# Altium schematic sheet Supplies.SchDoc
size A4
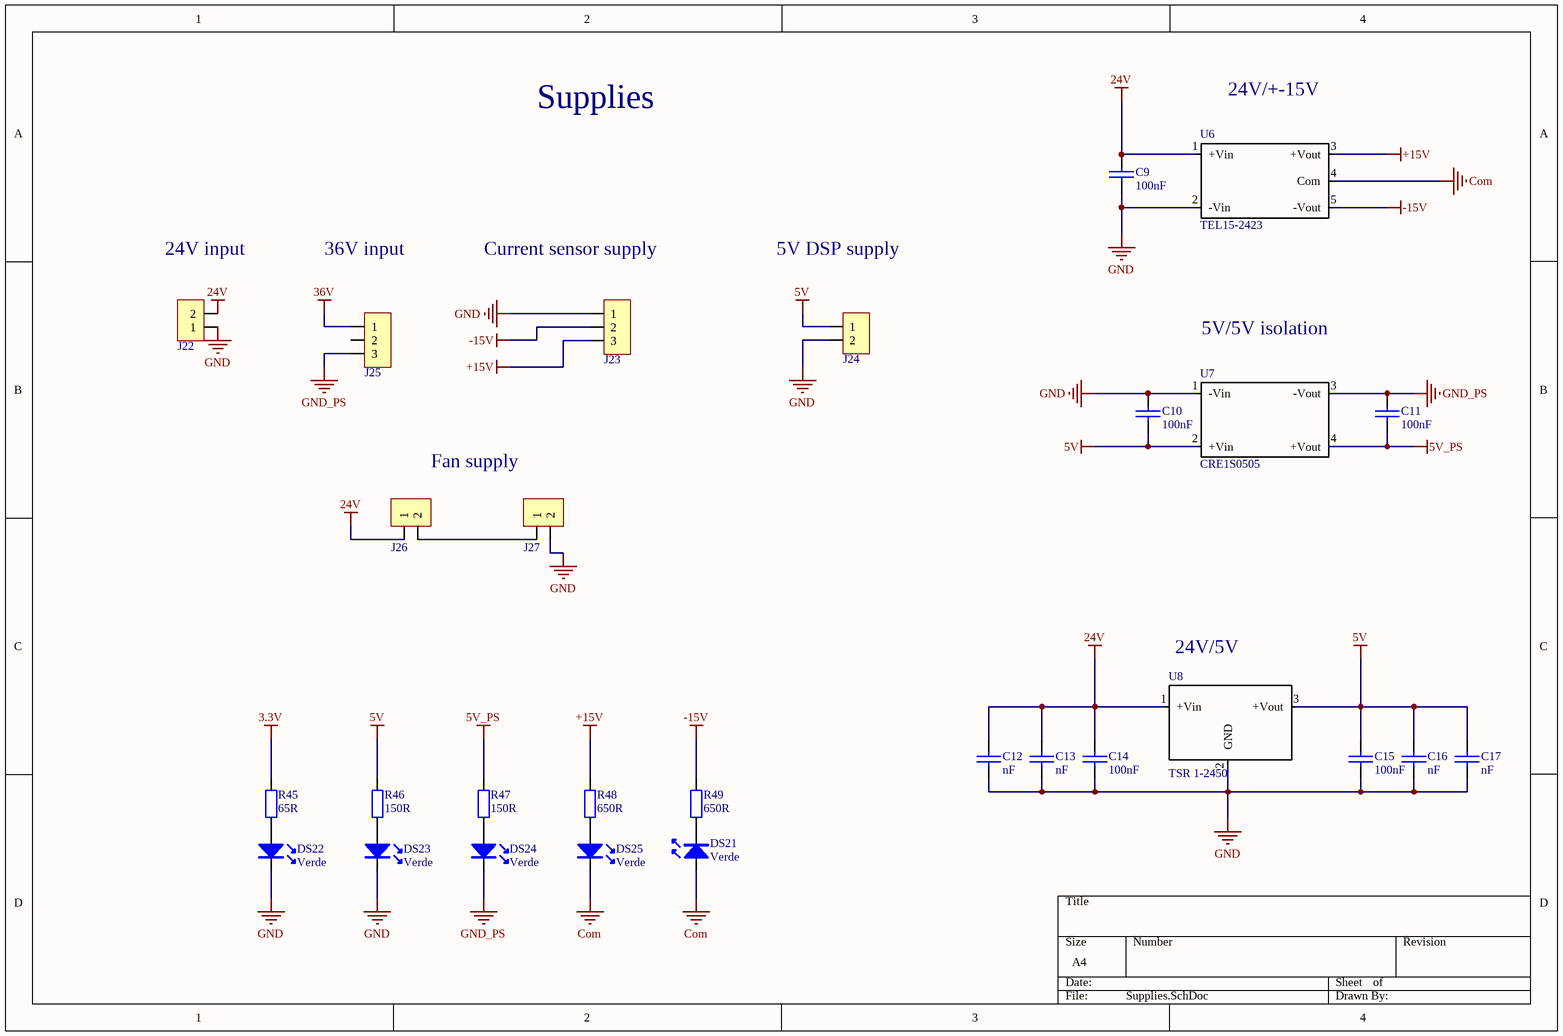
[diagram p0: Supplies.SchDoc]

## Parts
C9  100nF  [1206]
C10  100nF  [1206]
C11  100nF  [1206]
C12  nF  [1206]
C13  nF  [1206]
C14  100nF  [1206]
C15  100nF  [1206]
C16  nF  [1206]
C17  nF  [1206]
DS21  Verde  [LED_100mil]
DS22  Verde  [LED_100mil]
DS23  Verde  [LED_100mil]
DS24  Verde  [LED_100mil]
DS25  Verde  [LED_100mil]
J22  Cleva 2 vias  [Con2_ExtronSide_3.5mmPitch]  (value not drawn)
J23  Cur_meas_con  [Con3_KK_256]  (value not drawn)
J24  Cleva 2 vias  [Clema_2_vias]  (value not drawn)
J25  Cleva 2 vias  [Con3_150milPitch]  (value not drawn)
J26  Cleva 2 vias  [Con2_KK_256]  (value not drawn)
J27  Cleva 2 vias  [Con2_KK_256]  (value not drawn)
R45  65R  [1206]
R46  150R  [1206]
R47  150R  [1206]
R48  650R  [1206]
R49  650R  [1206]
U6  TEL15-2423  [TEL15-2423]
U7  CRE1S0505  [CRE1S0505SC]
U8  TSR 1-2450  [TSR 1-2450]

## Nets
3.3V: R45.1
5V: C10.2 C15.1 C16.1 C17.1 J24.1 R46.1 U7.2(+Vin) U8.3(+Vout)
5V_PS: C11.2 R47.1 U7.4(+Vout)
24V: C9.1 C12.1 C13.1 C14.1 J22.2 J26.1 U6.1(+Vin) U8.1(+Vin)
36V: J25.1
+15V: J23.3 R48.1 U6.3(+Vout)
-15V: J23.2 R49.1 U6.5(-Vout)
Com: DS21.A DS25.K U6.4(Com)
GND: C9.2 C10.1 C12.2 C13.2 C14.2 C15.2 C16.2 C17.2 DS22.K DS23.K J22.1 J23.1 J24.2 J27.2 U6.2(-Vin) U7.1(-Vin) U8.2(GND)
GND_PS: C11.1 DS24.K J25.3 U7.3(-Vout)
NetDS21_K: DS21.K R49.2
NetDS22_A: DS22.A R45.2
NetDS23_A: DS23.A R46.2
NetDS24_A: DS24.A R47.2
NetDS25_A: DS25.A R48.2
NetJ26_2: J26.2 J27.1

Not connected (* = marked no-connect by the designer): J25 2

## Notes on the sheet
- Supplies
- (near U6) 24V/+-15V
- (near J22) 24V input
- 36V input
- (near J23) Current sensor supply
- 5V DSP supply
- 5V/5V isolation
- Fan supply
- (near U8) 24V/5V

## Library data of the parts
C9-C17 = Condensador
DS21-DS25 = Led
J22 J24 J26 J27 = Con_2
J23 J25 = Con_3
R45-R49 = Resistencia: Potencia: 1/4W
